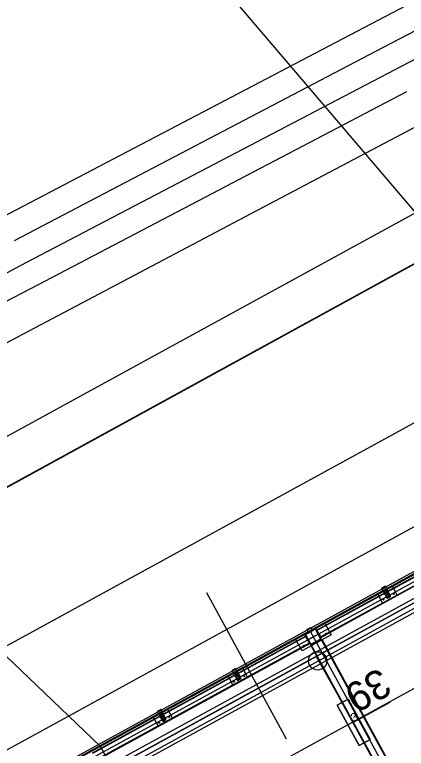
# Model space of a CAD drawing. Extents: x -783978 to -783565, y -1064821 to -1064596.
# Drawn here: x -783767.64 to -783762.94, y -1064681.64 to -1064672.84 of the extents above; entities that cross this region are included whole.
import ezdxf

# ---------------------------------------------------------------- set-up
doc = ezdxf.new("R2010")
doc.units = 0
for name, color, linetype in [('_PS_SO_číslo', 7, 'Continuous'), ('Default', 7, 'Continuous'), ('PS 01_01_10', 7, 'Continuous'), ('PS 01_02_501', 7, 'Continuous'), ('PS 01_02_502', 7, 'Continuous'), ('SO 01_11_01', 7, 'Continuous'), ('SO 01_20_01', 7, 'Continuous'), ('SO 01_50_01', 7, 'Continuous'), ('SO 01_74_01', 7, 'Continuous'), ('SO 01_86_03', 7, 'Continuous'), ('SO 01_86_04', 7, 'Continuous')]:
    doc.layers.add(name, color=color, linetype=linetype)

# ---------------------------------------------------------------- blocks, each defined once
blk = doc.blocks.new('POINT_DISPLAY')
at = {"layer": 'Default'}
blk.add_line((0, 0), (0, 0), dxfattribs=at)

msp = doc.modelspace()

# ---------------------------------------------------------------- linework, layer by layer
at = {"layer": '_PS_SO_číslo'}
for p, q in [((-783761.4118, -1064676.8772), (-783778.1513, -1064657.2448)), ((-783766.6153, -1064681.6172), (-783781.7427, -1064667.1516))]:
    msp.add_line(p, q, dxfattribs=at)
at = {"layer": 'PS 01_01_10'}
msp.add_lwpolyline([(-783718.9415, -1064658.9356), (-783725.9639, -1064662.6889), (-783732.3538, -1064665.9121), (-783735.2095, -1064660.6967), (-783789.362, -1064690.3481), (-783783.8255, -1064700.4409), (-783871.4362, -1064748.4249), (-783875.857, -1064749.8347)], dxfattribs=at)
at = {"layer": 'PS 01_02_501'}
msp.add_lwpolyline([(-783952.3105, -1064789.972), (-783925.027, -1064771.233), (-783922.857, -1064767.935), (-783921.1315, -1064767.225), (-783922.344, -1064769.056), (-783920.816, -1064771.043), (-783917.67, -1064770.417), (-783911.05, -1064766.471), (-783887.429, -1064753.525), (-783871.4362, -1064748.4249), (-783783.8277, -1064700.4386), (-783789.362, -1064690.3481), (-783735.2263, -1064660.7067), (-783727.1901, -1064659.072), (-783724.297, -1064658.4835), (-783715.521, -1064653.988), (-783697.391, -1064644.148), (-783676.268, -1064633.506), (-783655.138, -1064621.894)], dxfattribs=at)
at = {"layer": 'PS 01_02_502'}
msp.add_lwpolyline([(-783952.3105, -1064789.972), (-783925.027, -1064771.233), (-783922.857, -1064767.935), (-783921.1315, -1064767.225), (-783922.344, -1064769.056), (-783920.816, -1064771.043), (-783917.67, -1064770.417), (-783911.05, -1064766.471), (-783887.429, -1064753.525), (-783871.4362, -1064748.4249), (-783783.8277, -1064700.4386), (-783789.362, -1064690.3481), (-783735.2263, -1064660.7067), (-783727.1901, -1064659.072), (-783724.297, -1064658.4835), (-783715.521, -1064653.988), (-783697.391, -1064644.148), (-783676.268, -1064633.506), (-783655.138, -1064621.894)], dxfattribs=at)
at = {"layer": 'SO 01_11_01'}
msp.add_line((-783772.8819, -1064683.2217), (-783730.898, -1064660.279), dxfattribs=at)
at = {"layer": 'SO 01_20_01'}
for p, q in [((-783735.0054, -1064663.7532), (-783787.4671, -1064692.4555)), ((-783735.2041, -1064664.4318), (-783786.7885, -1064692.6541)), ((-783786.6445, -1064692.9173), (-783735.3233, -1064664.839)), ((-783738.0171, -1064666.3812), (-783786.4402, -1064692.874)), ((-783786.421, -1064692.9091), (-783737.9979, -1064666.4163)), ((-783737.8741, -1064667.2605), (-783785.3352, -1064693.2269))]:
    msp.add_line(p, q, dxfattribs=at)
at = {"layer": 'SO 01_50_01'}
for p, q in [((-783786.7885, -1064692.6541), (-783725.4827, -1064659.1131)), ((-783763.2124, -1064673.2307), (-783758.781, -1064670.9131)), ((-783763.0734, -1064673.4965), (-783758.6419, -1064671.1789)), ((-783767.6438, -1064675.5484), (-783763.2124, -1064673.2307)), ((-783767.5048, -1064675.8142), (-783763.0734, -1064673.4965)), ((-783767.3657, -1064676.08), (-783762.9343, -1064673.7624)), ((-783766.6803, -1064677.3212), (-783762.2938, -1064674.9213)), ((-783766.6803, -1064677.3212), (-783762.2938, -1064674.9213)), ((-783766.6803, -1064677.3212), (-783762.2938, -1064674.9213)), ((-783766.6803, -1064677.3212), (-783762.2938, -1064674.9213)), ((-783771.9361, -1064678.1319), (-783767.5048, -1064675.8142)), ((-783771.7971, -1064678.3977), (-783767.3657, -1064676.08)), ((-783771.0667, -1064679.721), (-783766.6803, -1064677.3212)), ((-783771.0667, -1064679.721), (-783766.6803, -1064677.3212)), ((-783771.0667, -1064679.721), (-783766.6803, -1064677.3212)), ((-783771.0667, -1064679.721), (-783766.6803, -1064677.3212)), ((-783764.8564, -1064680.6549), (-783760.47, -1064678.255)), ((-783764.8563, -1064680.655), (-783760.4699, -1064678.2551)), ((-783764.8563, -1064680.655), (-783760.4699, -1064678.2551)), ((-783764.3764, -1064681.5322), (-783765.3363, -1064679.7776)), ((-783769.2428, -1064683.0547), (-783764.8564, -1064680.6549)), ((-783769.2427, -1064683.0548), (-783764.8563, -1064680.655)), ((-783769.2427, -1064683.0548), (-783764.8563, -1064680.655))]:
    msp.add_line(p, q, dxfattribs=at)
for points in [[(-783794.3819, -1064686.5598), (-783780.8826, -1064681.3208), (-783774.0998, -1064678.3857), (-783769.1333, -1064675.9708), (-783757.8448, -1064670.0584), (-783751.3522, -1064666.6411), (-783737.2286, -1064658.6226), (-783727.8486, -1064654.7427)], [(-783793.6214, -1064687.9539), (-783787.3633, -1064685.3707), (-783777.5473, -1064681.1546), (-783771.5481, -1064678.7844), (-783764.589, -1064675.1141), (-783753.2118, -1064669.1137), (-783738.363, -1064660.9207), (-783736.4019, -1064659.7667), (-783727.4333, -1064655.5486)]]:
    msp.add_lwpolyline(points, dxfattribs=at)
at = {"layer": 'SO 01_74_01'}
for p, q in [((-783735.2185, -1064664.4055), (-783786.6099, -1064692.5222)), ((-783786.6003, -1064692.5398), (-783735.2089, -1064664.423)), ((-783761.4493, -1064678.8193), (-783764.0153, -1064680.2232)), ((-783761.4463, -1064678.8248), (-783764.0123, -1064680.2288)), ((-783763.9704, -1064680.3054), (-783761.4043, -1064678.9015)), ((-783763.9673, -1064680.311), (-783761.4013, -1064678.907)), ((-783763.1912, -1064679.6982), (-783763.2351, -1064679.7222)), ((-783763.2351, -1064679.7222), (-783763.2159, -1064679.7573)), ((-783763.1864, -1064679.707), (-783763.2303, -1064679.731)), ((-783763.2303, -1064679.731), (-783763.2207, -1064679.7485)), ((-783763.2207, -1064679.7485), (-783763.1768, -1064679.7246)), ((-783763.2159, -1064679.7573), (-783763.172, -1064679.7333)), ((-783763.172, -1064679.7333), (-783763.1912, -1064679.6982)), ((-783763.1768, -1064679.7246), (-783763.1864, -1064679.707)), ((-783764.1343, -1064680.2142), (-783764.0904, -1064680.1902)), ((-783764.1151, -1064680.2493), (-783764.1343, -1064680.2142)), ((-783764.0712, -1064680.2253), (-783764.1151, -1064680.2493)), ((-783764.0904, -1064680.1902), (-783764.0712, -1064680.2253)), ((-783764.0153, -1064680.2232), (-783763.9673, -1064680.311)), ((-783764.0123, -1064680.2288), (-783763.9704, -1064680.3054)), ((-783764.1469, -1064680.2952), (-783766.713, -1064681.6991)), ((-783764.1439, -1064680.3007), (-783766.71, -1064681.7047)), ((-783764.0989, -1064680.383), (-783764.1469, -1064680.2952)), ((-783764.102, -1064680.3774), (-783764.1439, -1064680.3007)), ((-783764.0869, -1064680.4049), (-783763.9553, -1064680.3329)), ((-783764.0799, -1064680.401), (-783763.9624, -1064680.3367)), ((-783763.9624, -1064680.3367), (-783762.9544, -1064682.179)), ((-783763.9553, -1064680.3329), (-783762.9474, -1064682.1752)), ((-783766.668, -1064681.7813), (-783764.102, -1064680.3774)), ((-783766.665, -1064681.7869), (-783764.0989, -1064680.383)), ((-783763.079, -1064682.2472), (-783764.0869, -1064680.4049)), ((-783763.072, -1064682.2433), (-783764.0799, -1064680.401)), ((-783764.9896, -1064680.6822), (-783765.0335, -1064680.7062)), ((-783765.0335, -1064680.7062), (-783765.0143, -1064680.7413)), ((-783764.9848, -1064680.6909), (-783765.0287, -1064680.7149)), ((-783765.0191, -1064680.7325), (-783764.9752, -1064680.7085)), ((-783764.9704, -1064680.7173), (-783764.9896, -1064680.6822)), ((-783764.9752, -1064680.7085), (-783764.9848, -1064680.6909)), ((-783765.0287, -1064680.7149), (-783765.0191, -1064680.7325)), ((-783765.0143, -1064680.7413), (-783764.9704, -1064680.7173)), ((-783765.8888, -1064681.1741), (-783765.9327, -1064681.1981)), ((-783765.9327, -1064681.1981), (-783765.9135, -1064681.2332)), ((-783765.884, -1064681.1829), (-783765.9279, -1064681.2069)), ((-783765.9279, -1064681.2069), (-783765.9183, -1064681.2245)), ((-783765.9183, -1064681.2245), (-783765.8744, -1064681.2005)), ((-783765.9135, -1064681.2332), (-783765.8696, -1064681.2092)), ((-783765.8696, -1064681.2092), (-783765.8888, -1064681.1741)), ((-783765.8744, -1064681.2005), (-783765.884, -1064681.1829))]:
    msp.add_line(p, q, dxfattribs=at)
for points in [[(-783735.1681, -1064664.4976), (-783787.4762, -1064693.1159)], [(-783763.1803, -1064679.7379), (-783763.2076, -1064679.7528)], [(-783763.1773, -1064679.7434), (-783763.2045, -1064679.7583)], [(-783763.1939, -1064679.7453), (-783763.1459, -1064679.8331)], [(-783763.1341, -1064679.8158), (-783763.173, -1064679.7446)], [(-783763.1285, -1064679.8128), (-783763.1675, -1064679.7416)], [(-783763.2113, -1064679.7656), (-783763.1724, -1064679.8368)], [(-783763.2058, -1064679.7626), (-783763.1669, -1064679.8337)], [(-783763.148, -1064679.7772), (-783763.1919, -1064679.8012)], [(-783763.1626, -1064679.835), (-783763.1353, -1064679.8201)], [(-783763.1596, -1064679.8405), (-783763.1323, -1064679.8256)], [(-783764.1484, -1064680.2675), (-783764.0379, -1064680.2071)], [(-783764.1446, -1064680.2745), (-783764.034, -1064680.2141)], [(-783763.9913, -1064680.2671), (-783764.1229, -1064680.3391)], [(-783764.0931, -1064680.2373), (-783762.9412, -1064682.3428)], [(-783764.0931, -1064680.2373), (-783764.0211, -1064680.3689)], [(-783764.0286, -1064680.2157), (-783763.9681, -1064680.3262)], [(-783764.0216, -1064680.2118), (-783763.9611, -1064680.3224)], [(-783764.0927, -1064680.3944), (-783764.1532, -1064680.2838)], [(-783764.0857, -1064680.3905), (-783764.1462, -1064680.28)], [(-783763.9697, -1064680.3316), (-783764.0803, -1064680.3921)], [(-783763.9659, -1064680.3386), (-783764.0764, -1064680.3991)], [(-783765.0098, -1064680.7496), (-783764.9708, -1064680.8207)], [(-783764.9787, -1064680.7218), (-783765.006, -1064680.7367)], [(-783765.0042, -1064680.7465), (-783764.9653, -1064680.8177)], [(-783764.9757, -1064680.7273), (-783765.003, -1064680.7423)], [(-783764.9924, -1064680.7293), (-783764.9444, -1064680.817)], [(-783764.9464, -1064680.7611), (-783764.9903, -1064680.7851)], [(-783764.9325, -1064680.7997), (-783764.9714, -1064680.7286)], [(-783764.927, -1064680.7967), (-783764.9659, -1064680.7256)], [(-783764.961, -1064680.8189), (-783764.9337, -1064680.804)], [(-783764.958, -1064680.8245), (-783764.9307, -1064680.8095)], [(-783765.909, -1064681.2415), (-783765.87, -1064681.3127)], [(-783765.8779, -1064681.2138), (-783765.9052, -1064681.2287)], [(-783765.9034, -1064681.2385), (-783765.8645, -1064681.3096)], [(-783765.8749, -1064681.2193), (-783765.9022, -1064681.2342)], [(-783765.8916, -1064681.2212), (-783765.8436, -1064681.309)], [(-783765.8317, -1064681.2917), (-783765.8706, -1064681.2205)], [(-783765.8262, -1064681.2887), (-783765.8651, -1064681.2175)], [(-783765.8456, -1064681.2531), (-783765.8895, -1064681.2771)], [(-783765.8602, -1064681.3109), (-783765.833, -1064681.296)], [(-783765.8572, -1064681.3164), (-783765.8299, -1064681.3015)]]:
    msp.add_lwpolyline(points, dxfattribs=at)
for points in [[(-783763.1062, -1064679.6973), (-783763.2816, -1064679.7933), (-783763.2241, -1064679.8986), (-783763.0486, -1064679.8026)], [(-783763.8409, -1064680.2817), (-783764.1918, -1064680.4737), (-783764.2686, -1064680.3333), (-783763.9177, -1064680.1413)], [(-783764.9046, -1064680.6813), (-783765.0801, -1064680.7773), (-783765.0225, -1064680.8825), (-783764.847, -1064680.7865)], [(-783764.9704, -1064680.7173), (-783765.0143, -1064680.7413), (-783764.9663, -1064680.829), (-783764.9224, -1064680.805)], [(-783765.8038, -1064681.1732), (-783765.9793, -1064681.2692), (-783765.9217, -1064681.3745), (-783765.7462, -1064681.2785)], [(-783766.5385, -1064681.7576), (-783766.8894, -1064681.9496), (-783766.9662, -1064681.8092), (-783766.6153, -1064681.6172)]]:
    msp.add_lwpolyline(points, close=True, dxfattribs=at)
for centre, radius in [((-783763.0893, -1064679.7907), 0.006), ((-783763.2121, -1064679.8579), 0.006), ((-783763.9039, -1064680.2706), 0.01), ((-783764.1671, -1064680.4146), 0.01), ((-783764.8877, -1064680.7746), 0.006), ((-783765.0106, -1064680.8418), 0.006), ((-783765.9098, -1064681.3338), 0.006), ((-783765.787, -1064681.2666), 0.006)]:
    msp.add_circle(centre, radius, dxfattribs=at)
for centre, radius, start, end in [((-783763.1757, -1064679.7461), 0.00945, 28.68349, 118.68349), ((-783763.1757, -1064679.7461), 0.00315, 28.68349, 118.68349), ((-783763.203, -1064679.7611), 0.00945, 118.68349, 208.68349), ((-783763.203, -1064679.7611), 0.00315, 118.68349, 208.68349), ((-783763.1641, -1064679.8322), 0.00315, 208.68349, 298.68349), ((-783763.1368, -1064679.8173), 0.00315, 298.68349, 28.68349), ((-783763.1368, -1064679.8173), 0.00945, 298.68349, 28.68349), ((-783763.1641, -1064679.8322), 0.00945, 208.68349, 298.68349), ((-783764.1426, -1064680.2781), 0.012, 118.68349, 208.68349), ((-783764.1426, -1064680.2781), 0.004, 118.68349, 208.68349), ((-783764.0321, -1064680.2176), 0.012, 28.68349, 118.68349), ((-783764.0321, -1064680.2176), 0.004, 28.68349, 118.68349), ((-783763.9716, -1064680.3281), 0.004, 298.68349, 28.68349), ((-783763.9716, -1064680.3281), 0.012, 298.68349, 28.68349), ((-783764.0822, -1064680.3886), 0.012, 208.68349, 298.68349), ((-783764.0822, -1064680.3886), 0.004, 208.68349, 298.68349), ((-783765.0015, -1064680.745), 0.00945, 118.68349, 208.68349), ((-783765.0015, -1064680.745), 0.00315, 118.68349, 208.68349), ((-783764.9742, -1064680.7301), 0.00945, 28.68349, 118.68349), ((-783764.9742, -1064680.7301), 0.00315, 28.68349, 118.68349), ((-783764.9353, -1064680.8012), 0.00315, 298.68349, 28.68349), ((-783764.9353, -1064680.8012), 0.00945, 298.68349, 28.68349), ((-783764.9625, -1064680.8162), 0.00945, 208.68349, 298.68349), ((-783764.9625, -1064680.8162), 0.00315, 208.68349, 298.68349), ((-783765.9007, -1064681.237), 0.00945, 118.68349, 208.68349), ((-783765.9007, -1064681.237), 0.00315, 118.68349, 208.68349), ((-783765.8734, -1064681.2221), 0.00945, 28.68349, 118.68349), ((-783765.8734, -1064681.2221), 0.00315, 28.68349, 118.68349), ((-783765.8618, -1064681.3081), 0.00945, 208.68349, 298.68349), ((-783765.8618, -1064681.3081), 0.00315, 208.68349, 298.68349), ((-783765.8345, -1064681.2932), 0.00315, 298.68349, 28.68349), ((-783765.8345, -1064681.2932), 0.00945, 298.68349, 28.68349)]:
    msp.add_arc(centre, radius, start, end, dxfattribs=at)
at = {"layer": 'SO 01_86_03'}
for points in [[(-783722.5212, -1064661.7932), (-783724.8208, -1064663.0486), (-783735.2095, -1064660.6967), (-783787.333, -1064689.2371), (-783786.8168, -1064690.1799), (-783783.3595, -1064696.8031), (-783781.9388, -1064699.4088), (-783783.8277, -1064700.4386), (-783871.4362, -1064748.4249), (-783875.857, -1064749.8347), (-783877.5381, -1064747.3925), (-783875.857, -1064749.8347), (-783887.429, -1064753.525), (-783911.05, -1064766.471), (-783917.67, -1064770.417), (-783920.816, -1064771.043), (-783922.344, -1064769.056), (-783922.498, -1064767.051)], [(-783747.0305, -1064676.621), (-783747.6236, -1064677.108), (-783750.7299, -1064678.7824), (-783751.6662, -1064678.8522), (-783782.6812, -1064695.8307), (-783782.8877, -1064696.6917), (-783783.0615, -1064696.8198), (-783783.3595, -1064696.8031), (-783786.8168, -1064690.1799), (-783787.333, -1064689.2371), (-783735.2095, -1064660.6967), (-783724.8208, -1064663.0486), (-783722.5212, -1064661.7932)]]:
    msp.add_lwpolyline(points, dxfattribs=at)
at = {"layer": 'SO 01_86_04'}
for p, q in [((-783764.0224, -1064680.5406), (-783763.5667, -1064681.3474)), ((-783763.6381, -1064681.0514), (-783763.7697, -1064681.1234)), ((-783763.6381, -1064681.0514), (-783763.7697, -1064681.1234)), ((-783763.7697, -1064681.1234), (-783763.6381, -1064681.0514)), ((-783763.7697, -1064681.1234), (-783763.6381, -1064681.0514)), ((-783763.3742, -1064681.5339), (-783763.6381, -1064681.0514)), ((-783763.3742, -1064681.5339), (-783763.6381, -1064681.0514)), ((-783763.6381, -1064681.0514), (-783763.3742, -1064681.5339)), ((-783763.6381, -1064681.0514), (-783763.3742, -1064681.5339)), ((-783763.7697, -1064681.1234), (-783763.5058, -1064681.6059)), ((-783763.7697, -1064681.1234), (-783763.5058, -1064681.6059)), ((-783763.5058, -1064681.6059), (-783763.7697, -1064681.1234)), ((-783763.5058, -1064681.6059), (-783763.7697, -1064681.1234)), ((-783763.5719, -1064681.3286), (-783763.1333, -1064681.0887)), ((-783763.5058, -1064681.6059), (-783763.3742, -1064681.5339)), ((-783763.5058, -1064681.6059), (-783763.3742, -1064681.5339)), ((-783763.3742, -1064681.5339), (-783763.5058, -1064681.6059)), ((-783763.3742, -1064681.5339), (-783763.5058, -1064681.6059))]:
    msp.add_line(p, q, dxfattribs=at)
for points in [[(-783738.3222, -1064666.4797), (-783740.5325, -1064667.689), (-783743.1715, -1064669.1328), (-783745.7538, -1064670.5456), (-783748.4385, -1064672.0145), (-783751.0413, -1064673.4385), (-783753.6847, -1064674.8847), (-783756.3281, -1064676.3309), (-783758.9715, -1064677.7772), (-783761.6149, -1064679.2234), (-783764.2583, -1064680.6696), (-783766.9018, -1064682.1159), (-783769.4633, -1064683.5173), (-783772.109, -1064684.9648), (-783774.7882, -1064686.4306), (-783778.1382, -1064688.2722), (-783783.8139, -1064691.3971), (-783785.747, -1064692.4898)], [(-783747.063, -1064670.9765), (-783746.9575, -1064671.1681), (-783786.6893, -1064692.8619), (-783786.185, -1064693.7636)]]:
    msp.add_lwpolyline(points, dxfattribs=at)
msp.add_circle((-783764.0039, -1064680.5924), 0.1097, dxfattribs=at)

# ---------------------------------------------------------------- block references
at = {"layer": 'SO 01_86_04', "xscale": 0.010000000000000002, "yscale": 0.009999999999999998, "rotation": 28.683491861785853}
for p in [(-783763.6381, -1064681.0514), (-783763.6381, -1064681.0514), (-783763.7697, -1064681.1234), (-783763.7697, -1064681.1234), (-783763.3742, -1064681.5339), (-783763.3742, -1064681.5339), (-783763.5058, -1064681.6059), (-783763.5058, -1064681.6059)]:
    msp.add_blockref('POINT_DISPLAY', p, dxfattribs=at)

# ---------------------------------------------------------------- texts
at = {"layer": 'SO 01_86_04'}
for s, height, rotation, p in [('39', 0.351, 209.46001, (-783763.2568, -1064680.6655)), ('3', 0.1, 28.68349, (-783763.5719, -1064681.3286))]:
    msp.add_text(s, height=height, rotation=rotation, dxfattribs=at).set_placement(p)

doc.saveas('drawing.dxf')
